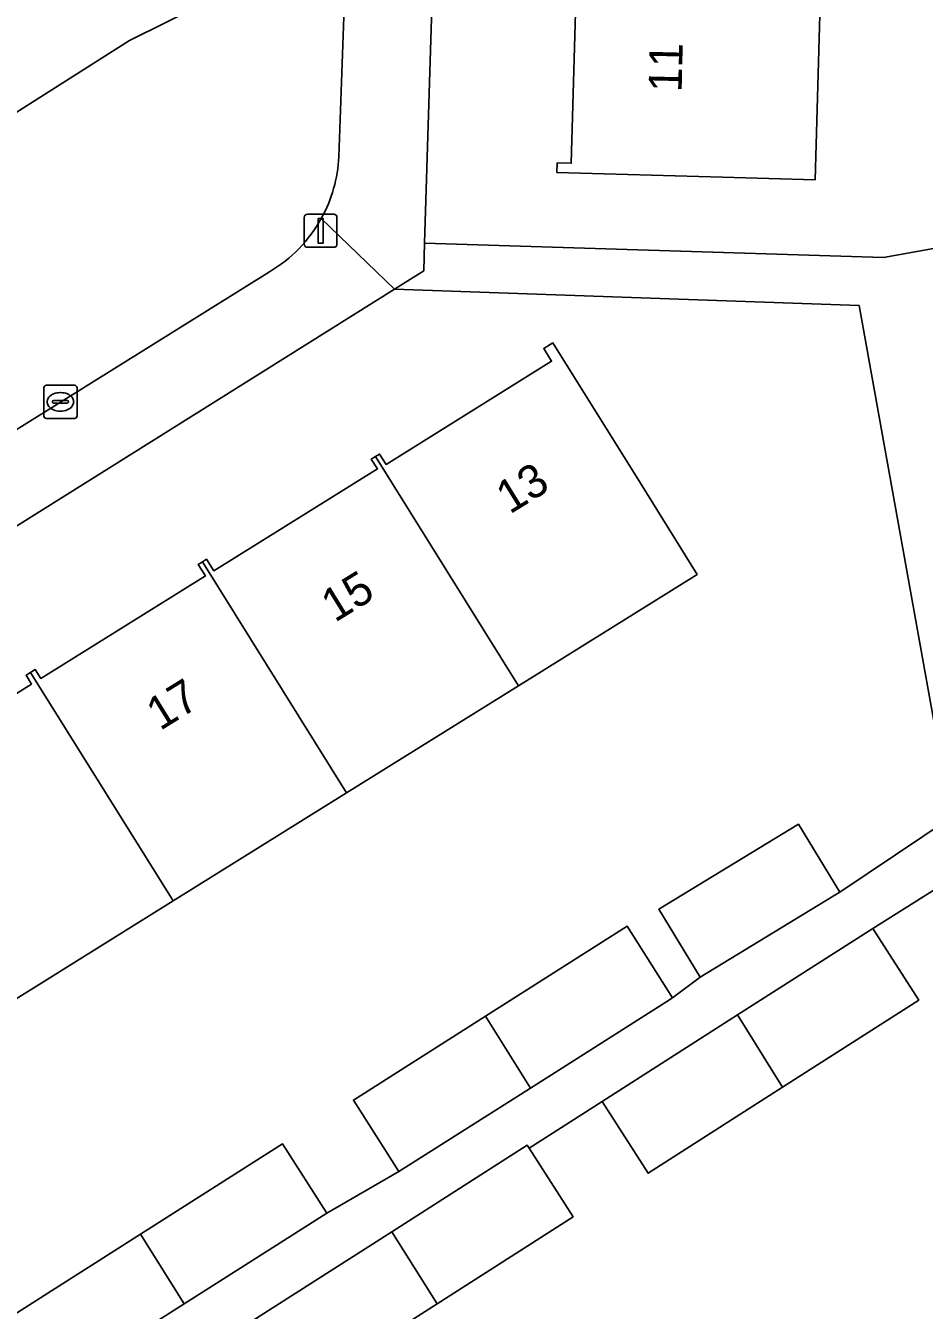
# Model space of a CAD drawing. Extents: x 160077 to 160948, y 386481 to 387498.
# Drawn here: x 160549.71 to 160576.85, y 386650.13 to 386688.94 of the extents above; entities that cross this region are included whole.
import ezdxf

# ---------------------------------------------------------------- set-up
doc = ezdxf.new("R2010")
doc.units = 0
for name, color, linetype in [('IMGEO_Erf', 7, 'Continuous'), ('IMGEO_Groenvoorziening', 7, 'Continuous'), ('IMGEO_Kolk', 7, 'Continuous'), ('IMGEO_Lichtmast', 7, 'Continuous'), ('IMGEO_Pand', 7, 'Continuous'), ('IMGEO_Pand_nummerreeks', 7, 'Continuous'), ('IMGEO_Voetpad_open', 7, 'Continuous')]:
    doc.layers.add(name, color=color, linetype=linetype)

msp = doc.modelspace()

# ---------------------------------------------------------------- linework, layer by layer
at = {"layer": 'IMGEO_Erf'}
for points in [[(160562.444, 386704.374), (160561.757, 386682.36), (160575.615, 386681.927), (160585.352, 386683.684), (160585.343, 386684.872), (160582.786, 386684.988), (160583.006, 386689.861), (160585.563, 386689.746), (160585.534, 386691.408), (160583.112, 386691.517)], [(160549.129, 386649.852), (160553.18, 386652.426), (160557.47, 386655.152), (160558.801, 386653.058), (160560.983, 386654.318), (160559.61, 386656.479), (160563.6, 386659.015), (160567.873, 386661.731), (160569.247, 386659.569), (160570.084, 386660.191), (160568.834, 386662.244), (160573.049, 386664.81), (160574.299, 386662.757), (160577.661, 386665.012), (160574.881, 386680.481), (160560.846, 386680.979), (160530.808, 386662.148), (160542.843, 386642.96)], [(160544.955, 386665.968), (160549.888, 386669.042), (160549.72, 386669.311), (160549.86, 386669.398), (160549.999, 386669.485), (160550.167, 386669.216), (160555.136, 386672.312), (160554.92, 386672.658), (160555.048, 386672.738), (160555.175, 386672.817), (160555.393, 386672.467), (160560.332, 386675.545), (160560.149, 386675.839), (160560.275, 386675.918), (160560.4, 386675.995), (160560.594, 386675.683), (160565.595, 386678.8), (160565.356, 386679.184), (160565.629, 386679.353), (160568.274, 386675.11), (160569.988, 386672.359), (160564.589, 386668.994), (160559.397, 386665.759), (160554.161, 386662.495), (160548.935, 386659.238)], [(160571.801, 386646.502), (160577.019, 386649.777), (160582.341, 386653.116), (160579.976, 386656.903), (160578.066, 386663.398), (160575.291, 386661.665), (160576.679, 386659.497), (160572.571, 386656.868), (160568.508, 386654.268), (160567.121, 386656.435), (160564.914, 386655.022), (160566.242, 386652.948), (160562.134, 386650.319), (160558.071, 386647.719), (160556.684, 386649.886), (160554.477, 386648.473), (160555.805, 386646.399), (160551.696, 386643.77), (160547.634, 386641.17), (160546.247, 386643.337), (160543.649, 386641.674), (160557.447, 386619.675), (160584.982, 386637.094)]]:
    msp.add_lwpolyline(points, dxfattribs=at)
msp.add_lwpolyline([(160573.737, 386690.689), (160573.554, 386684.279), (160570.751, 386684.359), (160565.753, 386684.501), (160565.762, 386684.793), (160566.189, 386684.781), (160566.359, 386690.743), (160565.919, 386690.755), (160565.924, 386690.908), (160565.928, 386691.059), (160566.299, 386691.049), (160566.465, 386696.876), (160566.118, 386696.886), (160566.121, 386696.98), (160566.124, 386697.077), (160566.46, 386697.067), (160566.628, 386702.969), (160566.315, 386702.978), (160566.324, 386703.311), (160574.09, 386703.09), (160574.07, 386702.373), (160577.816, 386702.266), (160577.656, 386696.656), (160573.91, 386696.762)], close=True, dxfattribs=at)
at = {"layer": 'IMGEO_Groenvoorziening'}
msp.add_lwpolyline([(160552.845, 386688.489), (160559.409, 386691.747), (160559.522, 386694.929), (160551.473, 386690.934), (160530.361, 386677.523), (160531.832, 386675.141)], close=True, dxfattribs=at)
msp.add_lwpolyline([(160559.169, 386684.978), (160559.409, 386691.747), (160552.845, 386688.489), (160531.832, 386675.141), (160536.017, 386668.363), (160557.078, 386681.502)], dxfattribs=at)
for centre, radius, start, end in [((160554.894, 386685.186), 4.28, 331.0427, 357.2127), ((160554.889, 386685.183), 4.283, 300.7338, 331.1079)]:
    msp.add_arc(centre, radius, start, end, dxfattribs=at)
at = {"layer": 'IMGEO_Kolk'}
for p, q in [((160550.26, 386677.145), (160550.26, 386677.997)), ((160550.335, 386678.071), (160551.187, 386678.071)), ((160550.748, 386677.851), (160550.773, 386677.851)), ((160551.261, 386677.997), (160551.261, 386677.145)), ((160550.519, 386677.565), (160550.519, 386677.577)), ((160550.957, 386677.528), (160550.559, 386677.528)), ((160550.562, 386677.614), (160550.96, 386677.614)), ((160551.003, 386677.577), (160551.003, 386677.565)), ((160551.187, 386677.071), (160550.335, 386677.071)), ((160550.771, 386677.291), (160550.746, 386677.291))]:
    msp.add_line(p, q, dxfattribs=at)
for points in [[(160550.26, 386677.145), (160550.26, 386677.997)], [(160550.335, 386678.071), (160551.187, 386678.071)], [(160551.261, 386677.997), (160551.261, 386677.145)], [(160551.187, 386677.071), (160550.335, 386677.071)]]:
    msp.add_lwpolyline(points, dxfattribs=at)
for centre, radius, start, end in [((160550.337, 386677.995), 0.0765, 91.552, 178.448), ((160550.337, 386677.995), 0.0765, 91.552, 178.448), ((160551.185, 386677.995), 0.0765, 1.552, 88.448), ((160551.185, 386677.995), 0.0765, 1.552, 88.448), ((160550.559, 386677.574), 0.0403, 85.8775, 175.7526), ((160550.556, 386677.564), 0.0366, 178.938, 274.7102), ((160550.96, 386677.571), 0.043, 264.8664, 352.4533), ((160550.964, 386677.576), 0.0386, 1.7309, 96.639), ((160550.337, 386677.147), 0.0765, 181.552, 268.448), ((160550.337, 386677.147), 0.0765, 181.552, 268.448), ((160551.185, 386677.147), 0.0765, 271.552, 358.448), ((160551.185, 386677.147), 0.0765, 271.552, 358.448)]:
    msp.add_arc(centre, radius, start, end, dxfattribs=at)
for centre, major_axis, ratio, start_param, end_param in [((160550.747, 386677.571), (-0.387, 0.002), 0.722429, 4.712389, 7.853982), ((160550.772, 386677.571), (-0.39, 0.002), 0.717154, 1.570796, 4.712389)]:
    msp.add_ellipse(centre, major_axis=major_axis, ratio=ratio, start_param=start_param, end_param=end_param, dxfattribs=at)
at = {"layer": 'IMGEO_Lichtmast'}
for p, q in [((160558.122, 386682.34), (160558.122, 386683.14)), ((160558.122, 386683.14), (160558.122, 386682.34)), ((160558.222, 386683.24), (160559.012, 386683.24)), ((160559.012, 386683.24), (160558.222, 386683.24)), ((160559.112, 386683.14), (160559.112, 386682.34)), ((160559.112, 386682.34), (160559.112, 386683.14)), ((160559.012, 386682.24), (160558.222, 386682.24)), ((160558.222, 386682.24), (160559.012, 386682.24))]:
    msp.add_line(p, q, dxfattribs=at)
msp.add_lwpolyline([(160558.542, 386683.115), (160558.692, 386683.115), (160558.692, 386682.365), (160558.542, 386682.365), (160558.542, 386683.115)], dxfattribs=at)
for centre, start, end in [((160558.222, 386683.14), 90, 180), ((160558.222, 386683.14), 90, 180), ((160559.012, 386683.14), 0, 90), ((160559.012, 386683.14), 360, 90), ((160558.222, 386682.34), 180, 270), ((160558.222, 386682.34), 180, 270), ((160559.012, 386682.34), 270, 0), ((160559.012, 386682.34), 270, 0)]:
    msp.add_arc(centre, 0.1, start, end, dxfattribs=at)
at = {"layer": 'IMGEO_Pand'}
for points in [[(160565.924, 386690.908), (160565.919, 386690.755), (160566.359, 386690.743), (160566.189, 386684.781), (160565.762, 386684.793), (160565.753, 386684.501), (160570.751, 386684.359), (160573.554, 386684.279), (160573.737, 386690.689)], [(160564.589, 386668.994), (160569.988, 386672.359), (160568.274, 386675.11), (160565.629, 386679.353), (160565.356, 386679.184), (160565.595, 386678.8), (160560.594, 386675.683), (160560.4, 386675.995), (160560.275, 386675.918)], [(160559.397, 386665.759), (160564.589, 386668.994), (160560.275, 386675.918), (160560.149, 386675.839), (160560.332, 386675.545), (160555.393, 386672.467), (160555.175, 386672.817), (160555.048, 386672.738)], [(160555.048, 386672.738), (160554.92, 386672.658), (160555.136, 386672.312), (160550.167, 386669.216), (160549.999, 386669.485), (160549.86, 386669.398), (160554.161, 386662.495), (160559.397, 386665.759)], [(160548.935, 386659.238), (160554.161, 386662.495), (160549.86, 386669.398), (160549.72, 386669.311), (160549.888, 386669.042), (160544.955, 386665.968), (160544.739, 386666.315), (160544.585, 386666.219)], [(160574.097, 386662.634), (160574.299, 386662.757), (160573.049, 386664.81), (160568.834, 386662.244), (160570.084, 386660.191)], [(160569.042, 386659.439), (160569.247, 386659.569), (160567.873, 386661.731), (160563.6, 386659.015), (160564.954, 386656.841)], [(160576.679, 386659.497), (160575.291, 386661.665), (160571.203, 386659.048), (160572.571, 386656.868)], [(160564.954, 386656.841), (160563.6, 386659.015), (160559.61, 386656.479), (160560.983, 386654.318)], [(160567.121, 386656.435), (160568.508, 386654.268), (160572.571, 386656.868), (160571.203, 386659.048)], [(160558.58, 386652.918), (160558.801, 386653.058), (160557.47, 386655.152), (160553.18, 386652.426), (160554.492, 386650.32)], [(160566.242, 386652.948), (160564.914, 386655.022), (160564.854, 386655.116), (160560.766, 386652.499), (160562.134, 386650.319)], [(160556.684, 386649.886), (160558.071, 386647.719), (160562.134, 386650.319), (160560.766, 386652.499)], [(160554.492, 386650.32), (160553.18, 386652.426), (160549.129, 386649.852), (160549.488, 386649.288), (160549.892, 386648.652), (160550.46, 386647.758)]]:
    msp.add_lwpolyline(points, close=True, dxfattribs=at)
at = {"layer": 'IMGEO_Voetpad_open'}
for points in [[(160558.639, 386683.114), (160560.846, 386680.979), (160561.731, 386681.534), (160561.757, 386682.36), (160562.444, 386704.374)], [(160559.522, 386694.929), (160559.409, 386691.747), (160559.169, 386684.978)], [(160585.352, 386683.684), (160575.615, 386681.927), (160561.757, 386682.36), (160561.731, 386681.534), (160560.846, 386680.979), (160574.881, 386680.481), (160577.661, 386665.012), (160574.299, 386662.757), (160574.097, 386662.634), (160570.084, 386660.191), (160569.247, 386659.569), (160569.042, 386659.439), (160564.954, 386656.841), (160560.983, 386654.318), (160558.801, 386653.058), (160558.58, 386652.918), (160554.492, 386650.32), (160550.46, 386647.758)], [(160560.846, 386680.979), (160558.639, 386683.114)], [(160557.078, 386681.502), (160536.017, 386668.363), (160534.378, 386667.381), (160525.541, 386661.6), (160523.682, 386660.442)], [(160524.968, 386658.378), (160526.956, 386659.637), (160527.678, 386660.188), (160529.243, 386661.168), (160530.808, 386662.148), (160560.846, 386680.979)], [(160571.203, 386659.048), (160575.291, 386661.665), (160578.066, 386663.398), (160579.976, 386656.903), (160582.341, 386653.116), (160584.482, 386649.704), (160587.14, 386645.468), (160591.082, 386639.771)], [(160556.684, 386649.886), (160560.766, 386652.499), (160564.854, 386655.116), (160564.914, 386655.022), (160567.121, 386656.435), (160571.203, 386659.048)]]:
    msp.add_lwpolyline(points, dxfattribs=at)
for centre, radius, start, end in [((160554.894, 386685.186), 4.28, 331.0427, 357.2127), ((160554.889, 386685.183), 4.283, 300.7338, 331.1079)]:
    msp.add_arc(centre, radius, start, end, dxfattribs=at)

# ---------------------------------------------------------------- texts
at = {"layer": 'IMGEO_Pand_nummerreeks'}
for s, rotation, p in [('11', 88.6091, (160569.52, 386686.923)), ('13', 31.7665, (160564.329, 386674.16)), ('15', 31.7665, (160559.049, 386670.89)), ('17', 31.7665, (160553.769, 386667.621))]:
    msp.add_text(s, height=1, rotation=rotation, dxfattribs=at).set_placement(p)

doc.saveas('drawing.dxf')
